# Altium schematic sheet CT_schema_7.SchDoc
size 368 x 245 mm
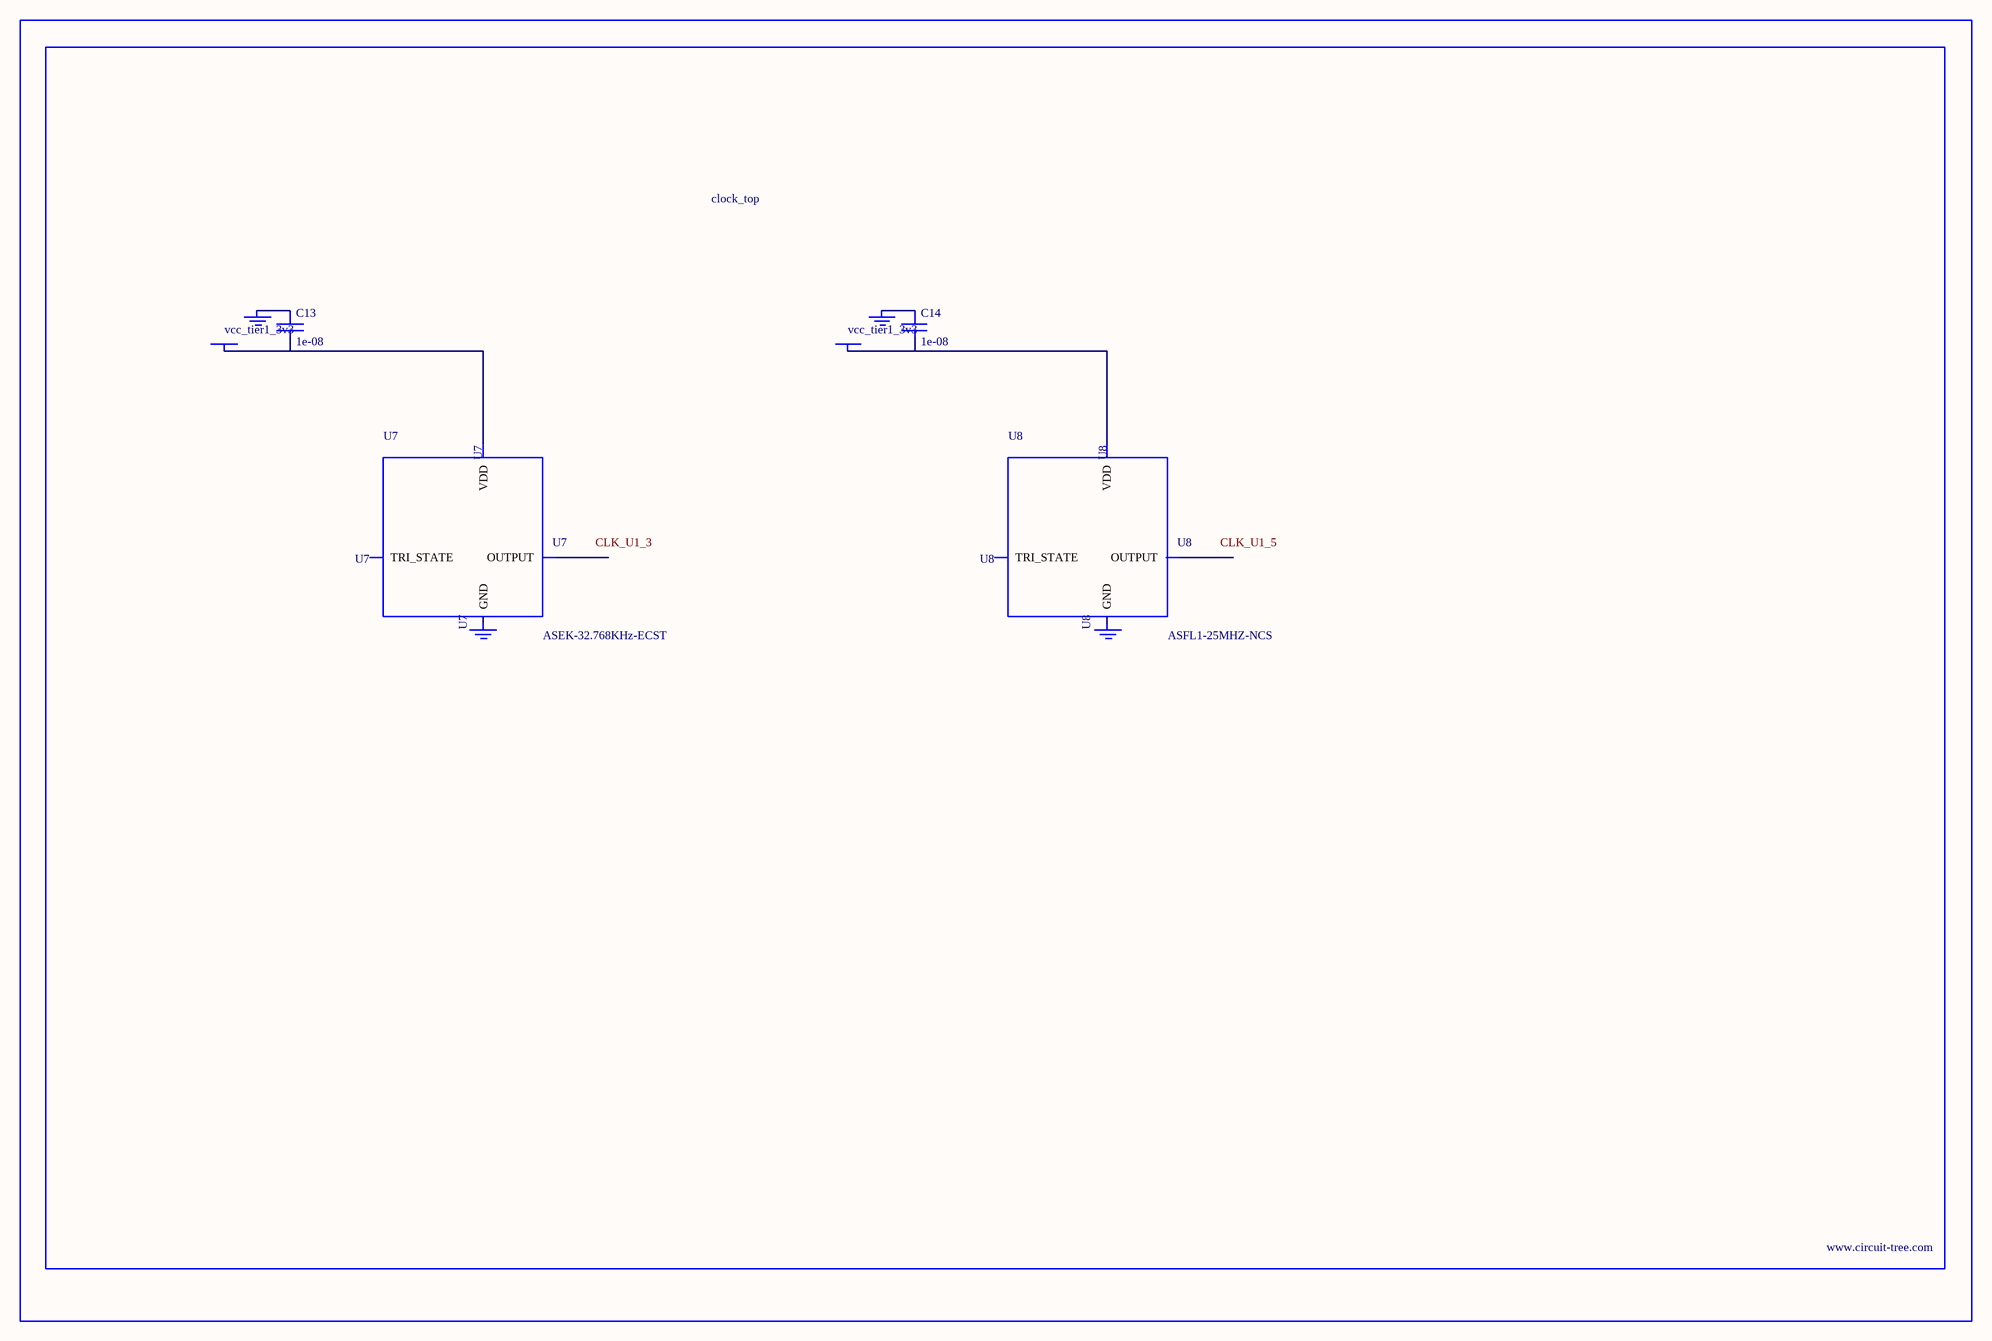
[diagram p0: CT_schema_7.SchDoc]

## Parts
BORDER6  (no value)
C13  1e-08  [C0402]
C14  1e-08  [C0402]
GND_INSTANCE_6_0  (no value)
GND_INSTANCE_6_1  (no value)
GND_INSTANCE_6_2  (no value)
GND_INSTANCE_6_3  (no value)
POWER_INSTANCE_6_0  vcc_tier1_3v3
POWER_INSTANCE_6_1  vcc_tier1_3v3
U7  ASEK-32.768KHz-ECST  [ASEK]
U8  ASFL1-25MHZ-NCS  [ASFL1]

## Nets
NetC13_1: C13.1 GND_INSTANCE_6_0.0(GND)
NetC13_2: C13.2 POWER_INSTANCE_6_0.0(PWR) U7.4(VDD)
NetC14_1: C14.1 GND_INSTANCE_6_2.0(GND)
NetC14_2: C14.2 POWER_INSTANCE_6_1.0(PWR) U8.4(VDD)

Not connected (* = marked no-connect by the designer): GND_INSTANCE_6_1 0(GND); GND_INSTANCE_6_3 0(GND); U7 1(TRI_STATE) 2(GND) 3(OUTPUT); U8 1(TRI_STATE) 2(GND) 3(OUTPUT)

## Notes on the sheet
- Labels drawn without touching a wire or pin: CLK_U1_3, CLK_U1_5

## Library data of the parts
BORDER6 = BORDER_PAGE6
C13 C14 = C0402C103K3RAC
GND_INSTANCE_6_0-GND_INSTANCE_6_3 = GND
POWER_INSTANCE_6_0 POWER_INSTANCE_6_1 = PWR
